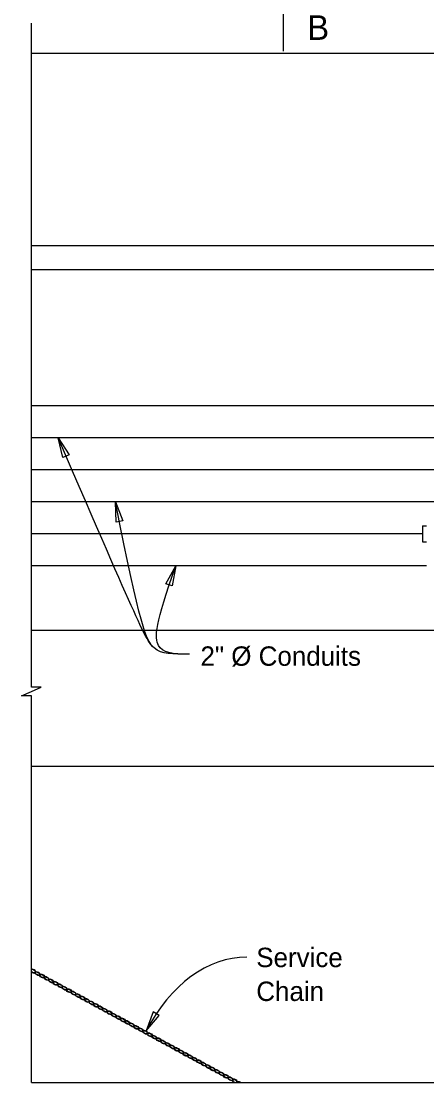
# Model space of a CAD drawing. Extents: x 0 to 20.5, y 0 to 13.
# Drawn here: x 5.81 to 7.91, y 3.07 to 8.64 of the extents above; entities that cross this region are included whole.
import ezdxf

# ---------------------------------------------------------------- set-up
doc = ezdxf.new("R2010")
doc.units = 0
for name, color, linetype in [('Dimension', 7, 'Continuous'), ('Miscellaneous', 7, 'Continuous'), ('NavLight', 7, 'Continuous'), ('NavLight_h', 7, 'Continuous'), ('SupstrConc', 7, 'Continuous'), ('TextStructures', 7, 'Continuous')]:
    doc.layers.add(name, color=color, linetype=linetype)

msp = doc.modelspace()

# ---------------------------------------------------------------- linework, layer by layer
at = {"layer": 'Dimension'}
msp.add_line((7.1685, 8.4857), (7.1685, 8.767), dxfattribs=at)
for points in [[(5.858, 3.1215), (5.858, 5.1331), (5.8063, 5.1331), (5.858, 5.1556), (5.9096, 5.1781), (5.858, 5.1781), (5.858, 8.6305)], [(5.858, 3.1215), (10.1884, 3.1215), (10.1884, 3.1731), (10.2109, 3.1215), (10.2334, 3.0698), (10.2334, 3.1215), (13.9245, 3.1215)]]:
    msp.add_lwpolyline(points, dxfattribs=at)
for points in [[(6.0221, 6.3723), (5.9969, 6.4749), (6.0544, 6.3863)], [(6.2987, 6.0359), (6.2961, 6.1415), (6.3334, 6.0427)], [(6.5576, 5.7159), (6.6089, 5.8082), (6.5909, 5.7041)], [(6.4541, 3.3905), (6.5221, 3.4714), (6.4917, 3.4893)]]:
    msp.add_lwpolyline(points, close=True, dxfattribs=at)
msp.add_ellipse((6.9793, 2.7441), major_axis=(0.001, -1.0298), ratio=0.654738, start_param=3.141603, end_param=4.033059, dxfattribs=at)
for points in [[(6.6802, 5.3497), (6.5898, 5.3497), (6.4854, 5.3437), (6.422, 5.493), (5.9969, 6.4749)], [(6.6802, 5.3497), (6.5898, 5.3497), (6.4863, 5.3438), (6.4231, 5.4905), (6.2961, 6.1415)], [(6.6802, 5.3497), (6.5898, 5.3497), (6.4908, 5.3622), (6.5026, 5.5069), (6.6089, 5.8082)]]:
    msp.add_open_spline(points, degree=3, dxfattribs=at)
at = {"layer": 'Miscellaneous'}
for centre, major_axis, ratio, start_param, end_param in [((5.8672, 3.7014), (-0.0135, 0.0073), 0.530594, 1.136711, 5.709865), ((5.8672, 3.7014), (-0.0117, 0.0064), 0.458548, 0.945695, 5.827628), ((6.9167, 3.129), (-0.0135, 0.0073), 0.530594, 3.116324, 7.906784), ((6.9167, 3.129), (-0.0117, 0.0064), 0.458548, 2.883494, 8.284687), ((6.94, 3.1163), (-0.0135, 0.0073), 0.530594, 4.474354, 6.548754), ((6.94, 3.1163), (-0.0117, 0.0064), 0.458548, 4.690379, 6.477803)]:
    msp.add_ellipse(centre, major_axis=major_axis, ratio=ratio, start_param=start_param, end_param=end_param, dxfattribs=at)
for centre, major_axis, ratio in [((5.8905, 3.6887), (-0.0135, 0.0073), 0.530594), ((5.8905, 3.6887), (-0.0117, 0.0064), 0.458548), ((5.9138, 3.676), (-0.0135, 0.0073), 0.530594), ((5.9138, 3.676), (-0.0117, 0.0064), 0.458548), ((5.9371, 3.6633), (-0.0135, 0.0073), 0.530594), ((5.9371, 3.6633), (-0.0117, 0.0064), 0.458548), ((5.9605, 3.6505), (-0.0135, 0.0073), 0.530594), ((5.9605, 3.6505), (-0.0117, 0.0064), 0.458548), ((5.9838, 3.6378), (-0.0135, 0.0073), 0.530594), ((5.9838, 3.6378), (-0.0117, 0.0064), 0.458548), ((6.0071, 3.6251), (-0.0135, 0.0073), 0.530594), ((6.0071, 3.6251), (-0.0117, 0.0064), 0.458548), ((6.0304, 3.6124), (-0.0135, 0.0073), 0.530594), ((6.0304, 3.6124), (-0.0117, 0.0064), 0.458548), ((6.0538, 3.5997), (-0.0135, 0.0073), 0.530594), ((6.0538, 3.5997), (-0.0117, 0.0064), 0.458548), ((6.0771, 3.5869), (-0.0135, 0.0073), 0.530594), ((6.0771, 3.5869), (-0.0117, 0.0064), 0.458548), ((6.1004, 3.5742), (-0.0135, 0.0073), 0.530594), ((6.1004, 3.5742), (-0.0117, 0.0064), 0.458548), ((6.1237, 3.5615), (-0.0135, 0.0073), 0.530594), ((6.1237, 3.5615), (-0.0117, 0.0064), 0.458548), ((6.147, 3.5488), (-0.0135, 0.0073), 0.530594), ((6.147, 3.5488), (-0.0117, 0.0064), 0.458548), ((6.1704, 3.5361), (-0.0135, 0.0073), 0.530594), ((6.1704, 3.5361), (-0.0117, 0.0064), 0.458548), ((6.1937, 3.5233), (-0.0135, 0.0073), 0.530594), ((6.1937, 3.5233), (-0.0117, 0.0064), 0.458548), ((6.217, 3.5106), (-0.0135, 0.0073), 0.530594), ((6.217, 3.5106), (-0.0117, 0.0064), 0.458548), ((6.2403, 3.4979), (-0.0135, 0.0073), 0.530594), ((6.2403, 3.4979), (-0.0117, 0.0064), 0.458548), ((6.2637, 3.4852), (-0.0135, 0.0073), 0.530594), ((6.2637, 3.4852), (-0.0117, 0.0064), 0.458548), ((6.287, 3.4724), (-0.0135, 0.0073), 0.530594), ((6.287, 3.4724), (-0.0117, 0.0064), 0.458548), ((6.3103, 3.4597), (-0.0135, 0.0073), 0.530594), ((6.3103, 3.4597), (-0.0117, 0.0064), 0.458548), ((6.3336, 3.447), (-0.0135, 0.0073), 0.530594), ((6.3336, 3.447), (-0.0117, 0.0064), 0.458548), ((6.357, 3.4343), (-0.0135, 0.0073), 0.530594), ((6.357, 3.4343), (-0.0117, 0.0064), 0.458548), ((6.3803, 3.4216), (-0.0135, 0.0073), 0.530594), ((6.3803, 3.4216), (-0.0117, 0.0064), 0.458548), ((6.4036, 3.4088), (-0.0135, 0.0073), 0.530594), ((6.4036, 3.4088), (-0.0117, 0.0064), 0.458548), ((6.4269, 3.3961), (-0.0135, 0.0073), 0.530594), ((6.4269, 3.3961), (-0.0117, 0.0064), 0.458548), ((6.4502, 3.3834), (-0.0135, 0.0073), 0.530594), ((6.4502, 3.3834), (-0.0117, 0.0064), 0.458548), ((6.4736, 3.3707), (-0.0135, 0.0073), 0.530594), ((6.4736, 3.3707), (-0.0117, 0.0064), 0.458548), ((6.4969, 3.358), (-0.0135, 0.0073), 0.530594), ((6.4969, 3.358), (-0.0117, 0.0064), 0.458548), ((6.5202, 3.3452), (-0.0135, 0.0073), 0.530594), ((6.5202, 3.3452), (-0.0117, 0.0064), 0.458548), ((6.5435, 3.3325), (-0.0135, 0.0073), 0.530594), ((6.5435, 3.3325), (-0.0117, 0.0064), 0.458548), ((6.5669, 3.3198), (-0.0135, 0.0073), 0.530594), ((6.5669, 3.3198), (-0.0117, 0.0064), 0.458548), ((6.5902, 3.3071), (-0.0135, 0.0073), 0.530594), ((6.5902, 3.3071), (-0.0117, 0.0064), 0.458548), ((6.6135, 3.2944), (-0.0135, 0.0073), 0.530594), ((6.6135, 3.2944), (-0.0117, 0.0064), 0.458548), ((6.6368, 3.2816), (-0.0135, 0.0073), 0.530594), ((6.6368, 3.2816), (-0.0117, 0.0064), 0.458548), ((6.6602, 3.2689), (-0.0135, 0.0073), 0.530594), ((6.6602, 3.2689), (-0.0117, 0.0064), 0.458548), ((6.6835, 3.2562), (-0.0135, 0.0073), 0.530594), ((6.6835, 3.2562), (-0.0117, 0.0064), 0.458548), ((6.7068, 3.2435), (-0.0135, 0.0073), 0.530594), ((6.7068, 3.2435), (-0.0117, 0.0064), 0.458548), ((6.7301, 3.2308), (-0.0135, 0.0073), 0.530594), ((6.7301, 3.2308), (-0.0117, 0.0064), 0.458548), ((6.7534, 3.218), (-0.0135, 0.0073), 0.530594), ((6.7534, 3.218), (-0.0117, 0.0064), 0.458548), ((6.7768, 3.2053), (-0.0135, 0.0073), 0.530594), ((6.7768, 3.2053), (-0.0117, 0.0064), 0.458548), ((6.8001, 3.1926), (-0.0135, 0.0073), 0.530594), ((6.8001, 3.1926), (-0.0117, 0.0064), 0.458548), ((6.8234, 3.1799), (-0.0135, 0.0073), 0.530594), ((6.8234, 3.1799), (-0.0117, 0.0064), 0.458548), ((6.8467, 3.1672), (-0.0135, 0.0073), 0.530594), ((6.8467, 3.1672), (-0.0117, 0.0064), 0.458548), ((6.8701, 3.1544), (-0.0135, 0.0073), 0.530594), ((6.8701, 3.1544), (-0.0117, 0.0064), 0.458548), ((6.8934, 3.1417), (-0.0135, 0.0073), 0.530594), ((6.8934, 3.1417), (-0.0117, 0.0064), 0.458548)]:
    msp.add_ellipse(centre, major_axis=major_axis, ratio=ratio, dxfattribs=at)
at = {"layer": 'NavLight'}
for p, q in [((7.892, 6.0165), (7.892, 5.9332)), ((7.892, 6.0165), (7.9129, 6.0165)), ((7.892, 5.9332), (7.9129, 5.9332))]:
    msp.add_line(p, q, dxfattribs=at)
at = {"layer": 'NavLight_h'}
for p, q in [((10.7406, 6.6416), (5.858, 6.6416)), ((10.7406, 6.4749), (5.858, 6.4749)), ((10.7406, 6.3082), (5.858, 6.3082)), ((10.7406, 6.1415), (5.858, 6.1415)), ((7.892, 5.9749), (5.858, 5.9749)), ((7.9129, 5.8082), (5.858, 5.8082))]:
    msp.add_line(p, q, dxfattribs=at)
at = {"layer": 'SupstrConc'}
for p, q in [((5.858, 8.4748), (13.9245, 8.4748)), ((5.858, 7.4748), (13.9245, 7.4748)), ((5.858, 7.3498), (11.7507, 7.3498)), ((5.858, 5.4749), (8.0838, 5.4749)), ((5.858, 4.7666), (8.0838, 4.7666))]:
    msp.add_line(p, q, dxfattribs=at)

# ---------------------------------------------------------------- texts
at = {"layer": 'Dimension'}
for s, p in [('Service', (7.0276, 3.7221)), ('Chain', (7.0276, 3.5461))]:
    msp.add_text(s, height=0.1008, dxfattribs=at).set_placement(p)
at = {"layer": 'TextStructures'}
for s, height, p in [('B', 0.128, (7.2921, 8.5436)), ('2" Ø Conduits', 0.1008, (6.7373, 5.2891))]:
    msp.add_text(s, height=height, dxfattribs=at).set_placement(p)

doc.saveas('drawing.dxf')
